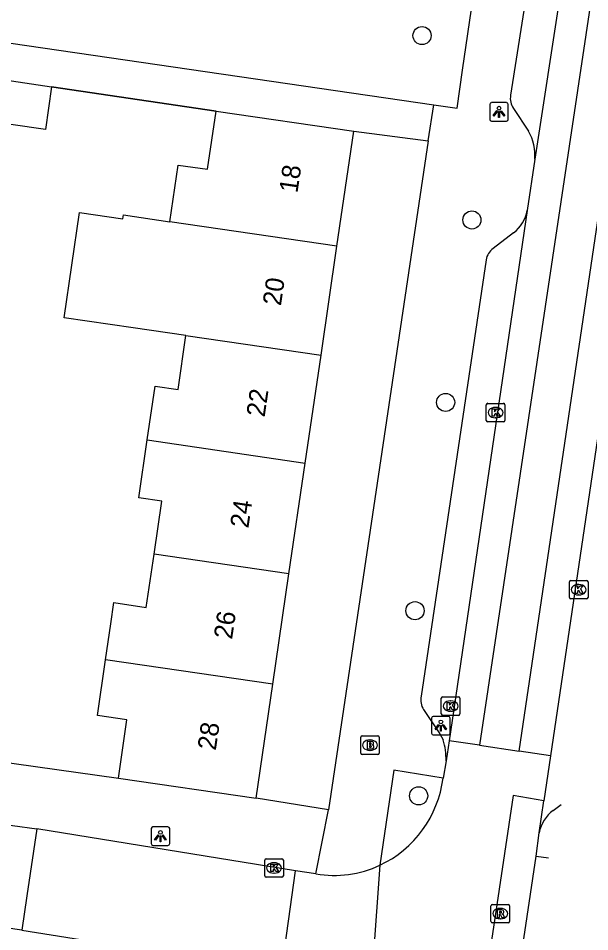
# Model space of a CAD drawing. Extents: x 163686 to 164493, y 382719 to 383870.
# Drawn here: x 164194.79 to 164225.56, y 382998.06 to 383047.3 of the extents above; entities that cross this region are included whole.
import ezdxf

# ---------------------------------------------------------------- set-up
doc = ezdxf.new("R2010")
doc.units = 0
for name, color, linetype in [('IMGEO_Boom', 7, 'Continuous'), ('IMGEO_Brandkraan', 7, 'Continuous'), ('IMGEO_Kolk', 7, 'Continuous'), ('IMGEO_Lichtpunt', 7, 'Continuous'), ('IMGEO_Muur', 7, 'Continuous'), ('IMGEO_Pand', 7, 'Continuous'), ('IMGEO_Pand_nummerreeks', 7, 'Continuous'), ('IMGEO_Rijbaan_lokaal_gesloten', 7, 'Continuous'), ('IMGEO_Rijbaan_lokaal_open', 7, 'Continuous'), ('IMGEO_Rioolput', 7, 'Continuous'), ('IMGEO_Voetpad_open', 7, 'Continuous')]:
    doc.layers.add(name, color=color, linetype=linetype)

msp = doc.modelspace()

# ---------------------------------------------------------------- linework, layer by layer
at = {"layer": 'IMGEO_Boom'}
for centre in [(164216.536, 383046.366), (164219.22, 383036.427), (164217.803, 383026.59), (164216.157, 383015.362), (164216.35, 383005.384)]:
    msp.add_circle(centre, 0.489, dxfattribs=at)
at = {"layer": 'IMGEO_Brandkraan'}
for p, q in [((164213.231, 383007.69), (164213.231, 383008.542)), ((164213.306, 383008.616), (164214.158, 383008.616)), ((164213.719, 383008.396), (164213.744, 383008.396)), ((164214.232, 383008.542), (164214.232, 383007.69)), ((164213.742, 383007.836), (164213.717, 383007.836)), ((164214.158, 383007.616), (164213.306, 383007.616))]:
    msp.add_line(p, q, dxfattribs=at)
for points in [[(164213.231, 383007.69), (164213.231, 383008.542)], [(164213.306, 383008.616), (164214.158, 383008.616)], [(164213.579, 383008.316), (164213.579, 383007.916), (164213.792, 383007.916)], [(164213.81, 383008.316), (164213.579, 383008.316)], [(164214.232, 383008.542), (164214.232, 383007.69)], [(164213.758, 383008.235), (164213.704, 383008.235), (164213.704, 383008.159)], [(164213.704, 383008.159), (164213.757, 383008.159)], [(164213.766, 383008.083), (164213.704, 383008.083), (164213.704, 383008.002)], [(164213.704, 383008.002), (164213.766, 383008.002)], [(164214.158, 383007.616), (164213.306, 383007.616)]]:
    msp.add_lwpolyline(points, dxfattribs=at)
for centre, radius, start, end in [((164213.308, 383008.54), 0.0765, 91.552, 178.448), ((164213.308, 383008.54), 0.0765, 91.552, 178.448), ((164213.814, 383008.171), 0.145, 59.4692, 91.5367), ((164213.839, 383008.218), 0.0922, 285.5137, 58.1501), ((164214.156, 383008.54), 0.0765, 1.552, 88.448), ((164214.156, 383008.54), 0.0765, 1.552, 88.448), ((164213.759, 383008.197), 0.0379, 267.8285, 90.9355), ((164213.767, 383008.042), 0.0404, 269.8759, 90.5077), ((164213.798, 383008.167), 0.251, 268.6676, 293.5347), ((164213.844, 383008.026), 0.105, 301.3115, 78.989), ((164213.308, 383007.692), 0.0765, 181.552, 268.448), ((164213.308, 383007.692), 0.0765, 181.552, 268.448), ((164214.156, 383007.692), 0.0765, 271.552, 358.448), ((164214.156, 383007.692), 0.0765, 271.552, 358.448)]:
    msp.add_arc(centre, radius, start, end, dxfattribs=at)
for centre, major_axis, ratio, start_param, end_param in [((164213.718, 383008.116), (-0.387, 0.002), 0.722429, 4.712389, 7.853982), ((164213.743, 383008.116), (-0.39, 0.002), 0.717154, 1.570796, 4.712389)]:
    msp.add_ellipse(centre, major_axis=major_axis, ratio=ratio, start_param=start_param, end_param=end_param, dxfattribs=at)
at = {"layer": 'IMGEO_Kolk'}
for p, q in [((164220.069, 383026.542), (164220.921, 383026.542)), ((164219.994, 383025.616), (164219.994, 383026.468)), ((164220.482, 383026.322), (164220.507, 383026.322)), ((164220.995, 383026.468), (164220.995, 383025.616)), ((164220.921, 383025.542), (164220.069, 383025.542)), ((164220.505, 383025.762), (164220.48, 383025.762)), ((164224.471, 383016.071), (164224.471, 383016.923)), ((164224.546, 383016.997), (164225.398, 383016.997)), ((164224.959, 383016.777), (164224.984, 383016.777)), ((164225.472, 383016.923), (164225.472, 383016.071)), ((164224.982, 383016.217), (164224.957, 383016.217)), ((164225.398, 383015.997), (164224.546, 383015.997)), ((164217.571, 383009.796), (164217.571, 383010.648)), ((164217.646, 383010.722), (164218.498, 383010.722)), ((164218.059, 383010.502), (164218.084, 383010.502)), ((164218.572, 383010.648), (164218.572, 383009.796)), ((164218.082, 383009.942), (164218.057, 383009.942)), ((164218.498, 383009.722), (164217.646, 383009.722)), ((164208.066, 383001.07), (164208.066, 383001.922)), ((164208.141, 383001.996), (164208.993, 383001.996)), ((164209.067, 383001.922), (164209.067, 383001.07)), ((164208.554, 383001.776), (164208.579, 383001.776)), ((164208.993, 383000.996), (164208.141, 383000.996)), ((164208.577, 383001.216), (164208.552, 383001.216))]:
    msp.add_line(p, q, dxfattribs=at)
for points in [[(164220.069, 383026.542), (164220.921, 383026.542)], [(164219.994, 383025.616), (164219.994, 383026.468)], [(164220.315, 383026.242), (164220.438, 383026.242), (164220.438, 383026.091), (164220.568, 383026.242), (164220.732, 383026.242), (164220.586, 383026.091), (164220.739, 383025.842), (164220.587, 383025.842), (164220.502, 383026.006), (164220.438, 383025.939), (164220.438, 383025.842), (164220.315, 383025.842), (164220.315, 383026.242)], [(164220.995, 383026.468), (164220.995, 383025.616)], [(164220.921, 383025.542), (164220.069, 383025.542)], [(164224.471, 383016.071), (164224.471, 383016.923)], [(164224.546, 383016.997), (164225.398, 383016.997)], [(164224.792, 383016.697), (164224.915, 383016.697), (164224.915, 383016.546), (164225.045, 383016.697), (164225.209, 383016.697), (164225.063, 383016.546), (164225.216, 383016.297), (164225.064, 383016.297), (164224.979, 383016.461), (164224.915, 383016.394), (164224.915, 383016.297), (164224.792, 383016.297), (164224.792, 383016.697)], [(164225.472, 383016.923), (164225.472, 383016.071)], [(164225.398, 383015.997), (164224.546, 383015.997)], [(164217.571, 383009.796), (164217.571, 383010.648)], [(164217.646, 383010.722), (164218.498, 383010.722)], [(164217.892, 383010.422), (164218.015, 383010.422), (164218.015, 383010.271), (164218.145, 383010.422), (164218.309, 383010.422), (164218.163, 383010.271), (164218.316, 383010.022), (164218.164, 383010.022), (164218.079, 383010.186), (164218.015, 383010.119), (164218.015, 383010.022), (164217.892, 383010.022), (164217.892, 383010.422)], [(164218.572, 383010.648), (164218.572, 383009.796)], [(164218.498, 383009.722), (164217.646, 383009.722)], [(164208.066, 383001.07), (164208.066, 383001.922)], [(164208.141, 383001.996), (164208.993, 383001.996)], [(164209.067, 383001.922), (164209.067, 383001.07)], [(164208.387, 383001.696), (164208.51, 383001.696), (164208.51, 383001.545), (164208.64, 383001.696), (164208.804, 383001.696), (164208.658, 383001.545), (164208.811, 383001.296), (164208.659, 383001.296), (164208.574, 383001.46), (164208.51, 383001.393), (164208.51, 383001.296), (164208.387, 383001.296), (164208.387, 383001.696)], [(164208.993, 383000.996), (164208.141, 383000.996)]]:
    msp.add_lwpolyline(points, dxfattribs=at)
for centre, start, end in [((164220.071, 383026.466), 91.552, 178.448), ((164220.071, 383026.466), 91.552, 178.448), ((164220.919, 383026.466), 1.552, 88.448), ((164220.919, 383026.466), 1.552, 88.448), ((164220.071, 383025.618), 181.552, 268.448), ((164220.071, 383025.618), 181.552, 268.448), ((164220.919, 383025.618), 271.552, 358.448), ((164220.919, 383025.618), 271.552, 358.448), ((164224.548, 383016.921), 91.552, 178.448), ((164224.548, 383016.921), 91.552, 178.448), ((164225.396, 383016.921), 1.552, 88.448), ((164225.396, 383016.921), 1.552, 88.448), ((164224.548, 383016.073), 181.552, 268.448), ((164224.548, 383016.073), 181.552, 268.448), ((164225.396, 383016.073), 271.552, 358.448), ((164225.396, 383016.073), 271.552, 358.448), ((164217.648, 383010.646), 91.552, 178.448), ((164217.648, 383010.646), 91.552, 178.448), ((164218.496, 383010.646), 1.552, 88.448), ((164218.496, 383010.646), 1.552, 88.448), ((164217.648, 383009.798), 181.552, 268.448), ((164217.648, 383009.798), 181.552, 268.448), ((164218.496, 383009.798), 271.552, 358.448), ((164218.496, 383009.798), 271.552, 358.448), ((164208.143, 383001.92), 91.552, 178.448), ((164208.143, 383001.92), 91.552, 178.448), ((164208.991, 383001.92), 1.552, 88.448), ((164208.991, 383001.92), 1.552, 88.448), ((164208.143, 383001.072), 181.552, 268.448), ((164208.143, 383001.072), 181.552, 268.448), ((164208.991, 383001.072), 271.552, 358.448), ((164208.991, 383001.072), 271.552, 358.448)]:
    msp.add_arc(centre, 0.0765, start, end, dxfattribs=at)
for centre, major_axis, ratio, start_param, end_param in [((164220.481, 383026.042), (-0.387, 0.002), 0.722429, 4.712389, 7.853982), ((164220.506, 383026.042), (-0.39, 0.002), 0.717154, 1.570796, 4.712389), ((164224.958, 383016.497), (-0.387, 0.002), 0.722429, 4.712389, 7.853982), ((164224.983, 383016.497), (-0.39, 0.002), 0.717154, 1.570796, 4.712389), ((164218.058, 383010.222), (-0.387, 0.002), 0.722429, 4.712389, 7.853982), ((164218.083, 383010.222), (-0.39, 0.002), 0.717154, 1.570796, 4.712389), ((164208.553, 383001.496), (-0.387, 0.002), 0.722429, 4.712389, 7.853982), ((164208.578, 383001.496), (-0.39, 0.002), 0.717154, 1.570796, 4.712389)]:
    msp.add_ellipse(centre, major_axis=major_axis, ratio=ratio, start_param=start_param, end_param=end_param, dxfattribs=at)
at = {"layer": 'IMGEO_Lichtpunt'}
for p, q in [((164221.082, 383042.75), (164220.274, 383042.75)), ((164221.082, 383042.75), (164220.274, 383042.75)), ((164220.18, 383042.655), (164220.18, 383041.848)), ((164220.18, 383042.655), (164220.18, 383041.848)), ((164221.176, 383041.848), (164221.176, 383042.655)), ((164221.176, 383041.848), (164221.176, 383042.655)), ((164220.274, 383041.754), (164221.082, 383041.754)), ((164220.274, 383041.754), (164221.082, 383041.754)), ((164217.049, 383009.568), (164217.049, 383008.761)), ((164217.049, 383009.568), (164217.049, 383008.761)), ((164217.951, 383009.663), (164217.143, 383009.663)), ((164217.951, 383009.663), (164217.143, 383009.663)), ((164218.045, 383008.761), (164218.045, 383009.568)), ((164218.045, 383008.761), (164218.045, 383009.568)), ((164217.143, 383008.667), (164217.951, 383008.667)), ((164217.143, 383008.667), (164217.951, 383008.667)), ((164201.95, 383003.616), (164201.95, 383002.809)), ((164201.95, 383003.616), (164201.95, 383002.809)), ((164202.852, 383003.711), (164202.044, 383003.711)), ((164202.852, 383003.711), (164202.044, 383003.711)), ((164202.946, 383002.809), (164202.946, 383003.616)), ((164202.946, 383002.809), (164202.946, 383003.616)), ((164202.044, 383002.715), (164202.852, 383002.715)), ((164202.044, 383002.715), (164202.852, 383002.715))]:
    msp.add_line(p, q, dxfattribs=at)
for points in [[(164220.554, 383042.319), (164220.593, 383042.291), (164220.405, 383042.029), (164220.367, 383042.056), (164220.554, 383042.319)], [(164220.656, 383042.271), (164220.703, 383042.271), (164220.703, 383041.949), (164220.656, 383041.949), (164220.656, 383042.271)], [(164220.766, 383042.291), (164220.804, 383042.318), (164220.991, 383042.056), (164220.952, 383042.028), (164220.766, 383042.291)], [(164217.423, 383009.232), (164217.462, 383009.204), (164217.274, 383008.942), (164217.236, 383008.969), (164217.423, 383009.232)], [(164217.525, 383009.184), (164217.572, 383009.184), (164217.572, 383008.862), (164217.525, 383008.862), (164217.525, 383009.184)], [(164217.635, 383009.204), (164217.673, 383009.231), (164217.86, 383008.969), (164217.821, 383008.941), (164217.635, 383009.204)], [(164202.324, 383003.28), (164202.363, 383003.252), (164202.175, 383002.99), (164202.137, 383003.017), (164202.324, 383003.28)], [(164202.426, 383003.232), (164202.473, 383003.232), (164202.473, 383002.91), (164202.426, 383002.91), (164202.426, 383003.232)], [(164202.536, 383003.252), (164202.574, 383003.279), (164202.761, 383003.017), (164202.722, 383002.989), (164202.536, 383003.252)]]:
    msp.add_lwpolyline(points, dxfattribs=at)
for centre in [(164220.679, 383042.453), (164217.548, 383009.366), (164202.449, 383003.414)]:
    msp.add_circle(centre, 0.0994, dxfattribs=at)
for centre, start, end in [((164220.274, 383042.655), 90, 180), ((164220.274, 383042.655), 90, 180), ((164221.082, 383042.655), 0, 90), ((164221.082, 383042.655), 0, 90), ((164220.274, 383041.848), 180, 270), ((164220.274, 383041.848), 180, 270), ((164221.082, 383041.848), 270, 0), ((164221.082, 383041.848), 270, 360), ((164217.143, 383009.568), 90, 180), ((164217.143, 383009.568), 90, 180), ((164217.951, 383009.568), 0, 90), ((164217.951, 383009.568), 0, 90), ((164217.143, 383008.761), 180, 270), ((164217.143, 383008.761), 180, 270), ((164217.951, 383008.761), 270, 0), ((164217.951, 383008.761), 270, 360), ((164202.044, 383003.616), 90, 180), ((164202.044, 383003.616), 90, 180), ((164202.852, 383003.616), 0, 90), ((164202.852, 383003.616), 0, 90), ((164202.044, 383002.809), 180, 270), ((164202.044, 383002.809), 180, 270), ((164202.852, 383002.809), 270, 0), ((164202.852, 383002.809), 270, 360)]:
    msp.add_arc(centre, 0.0946, start, end, dxfattribs=at)
at = {"layer": 'IMGEO_Muur'}
msp.add_lwpolyline([(164196.589, 383043.612), (164205.444, 383042.29)], dxfattribs=at)
at = {"layer": 'IMGEO_Pand'}
for points in [[(164192.969, 383044.135), (164196.589, 383043.612)], [(164196.589, 383043.612), (164196.255, 383041.296), (164192.634, 383041.819)], [(164202.957, 383036.331), (164203.402, 383039.388), (164204.986, 383039.157), (164205.444, 383042.29)], [(164205.444, 383042.29), (164212.862, 383041.205)], [(164211.956, 383035.014), (164212.862, 383041.205)], [(164203.822, 383030.198), (164200.985, 383030.613), (164197.264, 383031.157), (164198.095, 383036.836), (164200.431, 383036.494), (164200.46, 383036.696), (164202.957, 383036.331)], [(164211.956, 383035.014), (164202.957, 383036.331)], [(164211.095, 383029.134), (164211.956, 383035.014)], [(164201.738, 383024.57), (164202.162, 383027.472), (164203.397, 383027.292), (164203.822, 383030.198)], [(164203.822, 383030.198), (164211.095, 383029.134)], [(164210.245, 383023.325), (164211.095, 383029.134)], [(164202.105, 383018.41), (164202.522, 383021.26), (164201.28, 383021.442), (164201.738, 383024.57)], [(164201.738, 383024.57), (164210.245, 383023.325)], [(164209.371, 383017.347), (164210.245, 383023.325)], [(164199.497, 383012.713), (164199.781, 383014.659), (164199.947, 383015.797), (164201.685, 383015.543), (164202.105, 383018.41)], [(164209.371, 383017.347), (164202.105, 383018.41)], [(164208.5, 383011.396), (164209.371, 383017.347)], [(164200.183, 383006.341), (164200.643, 383009.481), (164199.059, 383009.712), (164199.497, 383012.713)], [(164208.5, 383011.396), (164199.497, 383012.713)], [(164207.601, 383005.255), (164208.5, 383011.396)], [(164200.183, 383006.341), (164207.601, 383005.255)]]:
    msp.add_lwpolyline(points, dxfattribs=at)
at = {"layer": 'IMGEO_Rijbaan_lokaal_gesloten'}
for points in [[(164225.582, 383058.271), (164227.096, 383058.067), (164219.624, 383008.118)], [(164221.77, 383007.795), (164229.165, 383057.742), (164230.838, 383057.493)], [(164225.375, 383057.735), (164222.604, 383039.696)], [(164222.604, 383039.696), (164222.193, 383036.944)], [(164222.193, 383036.944), (164217.988, 383008.345)], [(164226.062, 383025.136), (164223.448, 383007.533)], [(164219.624, 383008.118), (164217.988, 383008.345)], [(164223.448, 383007.533), (164221.77, 383007.795)], [(164223.09, 383005.122), (164221.436, 383005.393), (164219.005, 382989.047), (164220.204, 382988.86)], [(164222.834, 383003.398), (164223.09, 383005.122)], [(164222.675, 383002.126), (164222.834, 383003.398)], [(164221.531, 382994.431), (164222.675, 383002.126)]]:
    msp.add_lwpolyline(points, dxfattribs=at)
at = {"layer": 'IMGEO_Rijbaan_lokaal_open'}
for points in [[(164217.988, 383008.345), (164217.83, 383007.274)], [(164219.624, 383008.118), (164221.77, 383007.795)], [(164223.448, 383007.533), (164223.09, 383005.122)], [(164217.83, 383007.274), (164217.667, 383006.329)], [(164193.147, 383003.97), (164195.79, 383003.596)], [(164195.79, 383003.596), (164195.258, 383000), (164194.984, 382998.151)], [(164209.725, 383001.347), (164195.79, 383003.596)], [(164214.269, 383001.641), (164213.709, 382993.899)], [(164208.972, 382995.917), (164209.725, 383001.347)], [(164210.822, 383001.178), (164209.725, 383001.347)], [(164194.984, 382998.151), (164192.376, 382998.515)], [(164194.984, 382998.151), (164208.972, 382995.917)]]:
    msp.add_lwpolyline(points, dxfattribs=at)
for centre, radius, start, end in [((164211.662, 383007.106), 6.055, 295.5028, 352.6258), ((164211.804, 383006.931), 5.836, 260.3133, 294.987)]:
    msp.add_arc(centre, radius, start, end, dxfattribs=at)
at = {"layer": 'IMGEO_Rioolput'}
for p, q in [((164220.248, 382998.608), (164220.248, 382999.46)), ((164220.323, 382999.534), (164221.175, 382999.534)), ((164221.249, 382999.46), (164221.249, 382998.608)), ((164220.736, 382999.314), (164220.761, 382999.314)), ((164221.175, 382998.534), (164220.323, 382998.534)), ((164220.759, 382998.754), (164220.734, 382998.754))]:
    msp.add_line(p, q, dxfattribs=at)
for points in [[(164220.248, 382998.608), (164220.248, 382999.46)], [(164220.323, 382999.534), (164221.175, 382999.534)], [(164221.249, 382999.46), (164221.249, 382998.608)], [(164220.837, 382999.232), (164220.585, 382999.234), (164220.585, 382998.834)], [(164220.585, 382998.834), (164220.709, 382998.834), (164220.709, 382998.996), (164220.72, 382998.996)], [(164220.763, 382999.153), (164220.709, 382999.153), (164220.709, 382999.072)], [(164220.709, 382999.072), (164220.761, 382999.072)], [(164220.767, 382998.967), (164220.838, 382998.834), (164220.978, 382998.834), (164220.913, 382998.96)], [(164221.175, 382998.534), (164220.323, 382998.534)]]:
    msp.add_lwpolyline(points, dxfattribs=at)
for centre, radius, start, end in [((164220.325, 382999.458), 0.0765, 91.552, 178.448), ((164220.325, 382999.458), 0.0765, 91.552, 178.448), ((164221.173, 382999.458), 0.0765, 1.552, 88.448), ((164221.173, 382999.458), 0.0765, 1.552, 88.448), ((164220.719, 382998.943), 0.0533, 26.0293, 88.6989), ((164220.745, 382999.261), 0.19, 274.7715, 282.9687), ((164220.769, 382999.057), 0.0964, 77.0061, 93.1865), ((164220.783, 382999.114), 0.0378, 276.6634, 79.6772), ((164220.836, 382999.122), 0.109, 350.3612, 89.416), ((164220.834, 382999.122), 0.112, 277.5842, 350.9817), ((164220.818, 382998.907), 0.108, 29.5134, 73.7905), ((164220.325, 382998.61), 0.0765, 181.552, 268.448), ((164220.325, 382998.61), 0.0765, 181.552, 268.448), ((164221.173, 382998.61), 0.0765, 271.552, 358.448), ((164221.173, 382998.61), 0.0765, 271.552, 358.448)]:
    msp.add_arc(centre, radius, start, end, dxfattribs=at)
for centre, major_axis, ratio, start_param, end_param in [((164220.735, 382999.034), (-0.387, 0.002), 0.722429, 4.712389, 7.853982), ((164220.76, 382999.034), (-0.39, 0.002), 0.717154, 1.570796, 4.712389)]:
    msp.add_ellipse(centre, major_axis=major_axis, ratio=ratio, start_param=start_param, end_param=end_param, dxfattribs=at)
at = {"layer": 'IMGEO_Voetpad_open'}
for points in [[(164223.237, 383055.494), (164221.303, 383043.15)], [(164170.675, 383049.429), (164170.738, 383049.419), (164217.162, 383042.632)], [(164217.162, 383042.632), (164218.419, 383042.448), (164218.72, 383044.51), (164219.293, 383048.43)], [(164205.444, 383042.29), (164196.589, 383043.612)], [(164216.861, 383040.694), (164217.162, 383042.632)], [(164221.459, 383042.441), (164222.266, 383041.207)], [(164212.862, 383041.205), (164216.861, 383040.694)], [(164216.861, 383040.694), (164211.493, 383004.624)], [(164221.461, 383035.731), (164220.368, 383034.888)], [(164219.98, 383034.277), (164216.485, 383010.76)], [(164216.617, 383010.034), (164217.491, 383008.722), (164217.679, 383008.396)], [(164191.235, 383007.602), (164200.183, 383006.341)], [(164217.667, 383006.329), (164215.016, 383006.771), (164214.269, 383001.641)], [(164211.493, 383004.624), (164207.601, 383005.255)], [(164223.601, 383004.602), (164224.03, 383004.922)], [(164210.822, 383001.178), (164211.493, 383004.624)], [(164222.675, 383002.126), (164223.345, 383002.046)]]:
    msp.add_lwpolyline(points, dxfattribs=at)
for centre, radius, start, end in [((164222.255, 383042.988), 0.966, 170.3276, 214.4903), ((164220.132, 383039.936), 2.483, 354.4444, 30.7738), ((164220.288, 383037.266), 1.932, 307.3779, 350.4033), ((164220.947, 383034.091), 0.985, 126.0277, 169.1392), ((164217.445, 383010.56), 0.98, 168.2006, 212.4091), ((164214.031, 383007.334), 3.799, 359.0967, 16.2331), ((164224.884, 383002.938), 2.101, 127.6383, 167.3639)]:
    msp.add_arc(centre, radius, start, end, dxfattribs=at)

# ---------------------------------------------------------------- texts
at = {"layer": 'IMGEO_Pand_nummerreeks'}
for s, rotation, p in [('18', 81.6743, (164209.824, 383037.849)), ('20', 81.6751, (164208.934, 383031.767)), ('22', 81.6743, (164208.056, 383025.771)), ('24', 81.6743, (164207.181, 383019.781)), ('26', 81.6743, (164206.304, 383013.789)), ('28', 81.6743, (164205.427, 383007.801))]:
    msp.add_text(s, height=1, rotation=rotation, dxfattribs=at).set_placement(p)

doc.saveas('drawing.dxf')
